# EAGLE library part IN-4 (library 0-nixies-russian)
IN-4: large numeric topview nixie tube
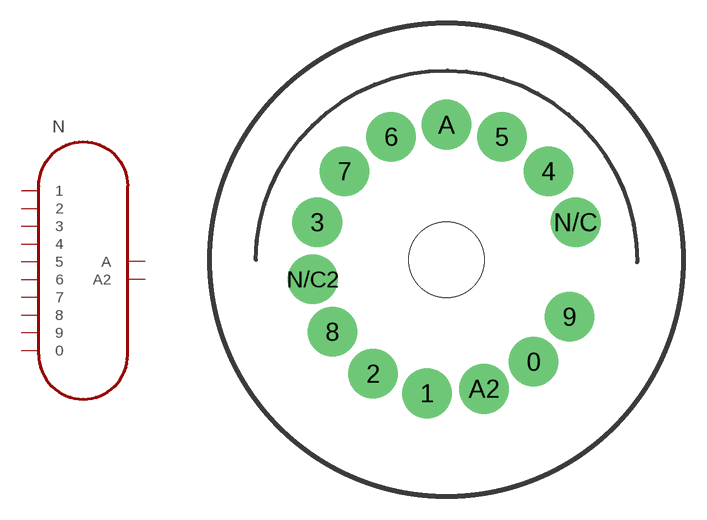
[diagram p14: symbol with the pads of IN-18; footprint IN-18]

Designator prefix N

## IN-4  [IN-18]
0  A
1  3
2  A2
4  6
5  8
6  9
7  7
8  2
9  1
A2  5
N/C  4
N/C2  0

## Footprint IN-18 (pad centres in mm)
May be used with socket: PL31-P
drill 2.3 pad 3.2 round: 0 5.8,-6.8; 1 -1.3,-8.9; 2 -4.9,-7.6; 3 -8.6,2.5; 4 6.8,5.9; 5 3.7,8.2; 6 -3.7,8.2; 7 -6.8,5.9; 8 -7.6,-4.8; 9 8.2,-3.8; A 0,9; A2 2.5,-8.6; N/C 8.6,2.5; N/C2 -8.9,-1.3
hole 5 at 0,0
